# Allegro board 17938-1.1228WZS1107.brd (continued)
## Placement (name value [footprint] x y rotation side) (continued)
C6318  SC10U6D3V3MX-DL-GP  [C603H36]  39.02 28.49 180 bottom
C6319  SC2D2U10V3KX-L-GP  [C603H36]  159.4 115.4 0 bottom
C6320  SCD1U16V2KX-L-GP  [C402H22]  151.05 111.74 180 bottom
C6321  SC2D2U10V3KX-L-GP  [C603H36]  160.62 115.4 0 bottom
C6322  SC4D7U6D3V3KX-L-GP  [C603H36]  156.92 119.58 90 bottom
C6323  SCD1U16V2KX-L-GP  [C402H22]  151.81 111.74 180 bottom
C6324  SC4D7U6D3V3KX-L-GP  [C603H36]  156.92 118.37 90 bottom
C6401  SCD1U16V2KX-3GP  [C402H22]  210.37 56.47 90 bottom
C6405  SC1U6D3V1MX-GP  [C0201H14]  23.73 60.12 90 bottom
C6501  SCD1U16V2KX-3GP  [C402H22]  85.39 37.69 90 top
C6503  SCD1U16V2KX-3DLGP  [C402H22]  96.45 31.4 90 top
C6505  SCD1U16V2KX-3GP  [C402H22]  105.86 29.17 180 top
C6506  SC10P50V2JN-4DLGP  [C402H22]  101.27 36.5 180 bottom
C6507  SC10P50V2JN-4DLGP  [C402H22]  71.28 37.67 0 bottom
C6508  SC10P50V2JN-4DLGP  [C402H22]  88.09 37.29 0 top
C7003  SCD1U16V2KX-3DLGP  [C402H22]  144.33 78.44 0 top
C7004  SC10U6D3V3MX-GP  [C603H38]  145.32 78.54 0 top
C7103  SCD1U16V2KX-3DLGP  [C402H22]  28.04 101.35 270 top
C7104  SCD1U16V2KX-3DLGP  [C402H22]  28.04 100.56 270 top
C7105  SCD1U16V2KX-3DLGP  [C402H22]  28.04 99.77 270 top
C7106  SCD1U16V2KX-3DLGP  [C402H22]  28.04 98.99 270 top
C7107  SCD1U16V2KX-3DLGP  [C402H22]  27.38 105.31 270 top
C7108  SCD1U16V2KX-3DLGP  [C402H22]  27.36 106.91 270 top
C7109  SCD1U16V2KX-3DLGP  [C402H22]  27.36 106.15 270 top
C7110  SCD1U16V2KX-3DLGP  [C402H22]  27.05 108.46 270 top
C7111  SCD1U16V2KX-3DLGP  [C402H22]  27.05 107.67 270 top
C7112  SCD1U16V2KX-3DLGP  [C402H22]  27.38 103 270 top
C7113  SCD1U16V2KX-3DLGP  [C402H22]  27.38 103.76 270 top
C7114  SCD1U16V2KX-3DLGP  [C402H22]  27.38 104.55 270 top
C7115  SCD1U16V2KX-3DLGP  [C402H22]  20.45 103.23 180 bottom
C7116  SCD1U16V2KX-3DLGP  [C402H22]  20.1 107.63 0 bottom
C7117  SCD1U16V2KX-3DLGP  [C402H22]  22.81 103.35 180 bottom
C7118  SCD1U16V2KX-3DLGP  [C402H22]  22.07 108.27 0 bottom
C7119  SC10U6D3V3MX-DL-GP  [C603H36]  21.09 108.06 180 bottom
C7120  SCD1U16V2KX-3DLGP  [C402H22]  33.75 121.57 180 top
C7161  SCD1U25V2KX-1-DL-GP  [C402H22]  17.68 104.7 90 top
C7162  SCD1U25V2KX-1-DL-GP  [C402H22]  17.68 105.49 90 top
C7163  SCD1U25V2KX-1-DL-GP  [C402H22]  17.68 106.27 90 top
C7164  SCD1U25V2KX-1-DL-GP  [C402H22]  17.68 107.06 90 top
C7165  SC2D2U6D3V2MX-DL-GP  [C402H22]  18.8 101.63 180 top
C7166  SCD1U25V2KX-1-DL-GP  [C402H22]  23.42 107.33 270 bottom
C7167  SCD33U25V1KX-1-GP-U  [C0201-TO0D1H16]  17.48 103.66 270 top
C7168  SCD33U25V1KX-1-GP-U  [C0201-TO0D1H16]  18.09 108.33 270 top
C7169  SCD33U25V1KX-1-GP-U  [C0201-TO0D1H16]  18.09 107.77 270 top
C7170  SCD33U25V1KX-1-GP-U  [C0201-TO0D1H16]  17.45 102.92 270 top
C7201  SCD1U25V2KX-1-DL-GP  [C402H22]  44.53 107.18 270 top
C7202  SC1U6D3V1MX-GP  [C0201H14]  42.19 107.25 0 top
C7203  SCD1U16V2KX-3DLGP  [C402H22]  38.49 106.03 270 top
C7204  SCD1U16V2KX-3DLGP  [C402H22]  38.49 107.63 270 top
C7205  SCD1U16V2KX-3DLGP  [C402H22]  43.86 125.51 180 top
C7206  SC10U6D3V2MX-2-GP  [C402-TO0D2H28]  44.84 125.92 180 top
C7207  SC1U10V2KX-1GP  [C402H22]  38.49 106.82 270 top
C7208  SC390P50V2KX-GP-U  [C402H24]  43.44 112.55 180 top
C7209  SC390P50V2KX-GP-U  [C402H24]  44.96 110.29 90 top
C7210  SCD1U16V2KX-3DLGP  [C402H22]  41.51 105.92 90 top
C7211  SCD1U16V2KX-3DLGP  [C402H22]  41.51 105.13 90 top
C7212  SC1U10V2KX-1GP  [C402H22]  40.38 105.13 0 top
C7213  SCD1U16V2KX-3DLGP  [C402H22]  42.91 114.28 180 top
C7214  SC1U50V3KX-GP  [C603H32]  49.8 127.04 90 top
C7215  SCD22U10V2KX-1GP  [C402H22]  46.36 133.4 0 top
C7216  SCD1U16V2KX-3DLGP  [C402H22]  52.69 127.81 0 top
C7217  SC2D2U6D3V2MX-DL-GP  [C402H22]  53.47 127.8 0 top
C7302  SCD1U25V2KX-1-DL-GP  [C402H22]  11.66 125.05 0 bottom
C7303  SCD1U25V2KX-1-DL-GP  [C402H22]  10.57 118.02 270 top
C7304  SCD1U25V2KX-1-DL-GP  [C402H22]  12.45 125.05 0 bottom
C7305  SC10U25V5KX-DL-GP  [C805H58]  12.56 113.51 270 bottom
C7306  SC1U50V3KX-1-GP  [C603H36]  10.56 113.46 180 bottom
C7307  SCD1U25V2KX-1-DL-GP  [C402H22]  10.57 117.24 270 top
C7401  SC1500P50V2KX-2-DL-GP  [C402H22]  33.54 124.3 0 top
C7403  SC22U6D3V3MX-1-DL-GP  [C603H40]  44.94 122.04 90 top
C7404  SC22U6D3V3MX-1-DL-GP  [C603H40]  45.19 123.82 0 top
C7405  SC1KP50V2KX-1GP  [C402H22]  39.09 120.27 0 top
C9104  SCD1U16V2KX-3DLGP  [C402H22]  153.67 145.44 0 bottom
C9106  SC10U6D3V3MX-DL-GP  [C603H36]  147.09 145.04 0 bottom
C9108  SC33P50V2JN-3DLGP  [C402H22]  148.09 145.72 0 bottom
C9109  SC4D7U6D3V3KX-DLGP  [C603H36]  152.28 142.67 270 top
C9112  SCD1U16V2KX-3DLGP  [C402H22]  151.9 143.69 270 top
C9113  SCD1U16V2KX-3DLGP  [C402H22]  149.15 137.52 90 bottom
C9201  SC1U6D3V1MX-GP  [C0201H14]  213.8 63.68 180 top
C9202  SC1U6D3V1MX-GP  [C0201H14]  214.34 63.69 180 top
C9203  SCD1U16V2KX-3DLGP  [C402H22]  221.53 67.27 0 top
CPU1  WHISKEY-LAKE-GP  [BGA1528M2446-1H52]  100.25 95.3 270 bottom
D1701  RB520S30-GP  [SOD523AKH26]  143.87 83.24 180 bottom
D1702  BAW56-9-GP-U  [SOT23-2D4-312H44]  54.17 83.77 90 bottom
D2401  BAT54C-12-GP  [SOT-23-9H44]  21.62 40.41 270 bottom
D2402  L1SS355T1G-GP  [SOD323AKH44]  131.9 39.29 270 bottom
D2403  RB551V30-GP  [SOD323AKH38]  25.53 55.14 315 top
D2404  BAW56-9-GP-U  [SOT23-2D4-312H44]  52.47 80.25 270 bottom
D2501  BAT54C-12-GP  [SOT-23-9H44]  158.13 79.56 180 bottom
D2502  RB751VM-40TE-17-GP  [SOD323-2513AKH36]  161.71 82.77 90 bottom
D2503  BAT54A-11-GP  [SOT-23-9H44]  158.78 92.55 90 bottom
D2601  RB551V30-GP  [SOD323AKH38]  161.22 92.3 180 bottom
D2703  BAT54C-12-GP  [SOT-23-9H44]  22.86 22.18 180 top
D2901  BAT54A-11-GP  [SOT-23-9H44]  25.1 6.71 0 top
D4001  L1SS355T1G-GP  [SOD323AKH44]  142.55 117.36 180 bottom
D4002  RB520S30-GP  [SOD523AKH26]  83.77 40.26 90 bottom
D4003  RB520S30-GP  [SOD523AKH26]  87.07 40.23 270 bottom
D4301  P6AF24A-R1-00001-GP  [D4724AKH44]  22.03 121.72 90 top
D4302  LBAV99LT1G-1-GP  [SOT23-2D4-312H44]  25.25 92.41 90 top
D4304  SMF18A-GP  [SOD123AK-2H43]  150.23 38.98 180 bottom
D4305  RB751V-40H-GP  [SOD323AKH38]  35.57 133.41 90 top
D4309  RB751V-40H-GP  [SOD323AKH38]  34.98 131.65 90 top
D5502  BAT54C-12-GP  [SOT-23-9H44]  144.86 89.69 270 top
D5503  BAT54C-12-GP  [SOT-23-9H44]  180.83 69.62 90 bottom
D5504  RB751S40T1G-GP  [D1608AK-UH28]  145.32 131.57 180 top
D5505  RB751S40T1G-GP  [D1608AK-UH28]  150.99 134.06 0 top
D5701  BAW56-9-GP-U  [SOT23-2D4-312H44]  18.16 91.11 0 top
D6401  BAT54A-11-GP  [SOT-23-9H44]  27.21 24.44 180 top
D6403  RB751VM-40TE-17-GP  [SOD323-2513AKH36]  17.05 50.41 0 bottom
D7201  SBA0520Q-R1-00001-GP-U  [D1006-0305AK-UH22]  54.45 127.88 0 top
D7202  SBA0520Q-R1-00001-GP-U  [D1006-0305AK-UH22]  55.27 126.09 270 top
D7401  SBA330AH-R1-00001-GP  [SOD123AK-3718-1H40]  41.1 125.96 270 top
DBEC1  ACES-CON6-58-GP  [50696-00601-001]  46.54 74.76 90 top
DBG1  DM-ACES-CON14-5-GP-02  [DM-87212-1400N-02]  63.63 67.97 0 bottom
DCIN1  ACES-CON8-13-GP-U2  [50224-0080N-W02-U]  20.7 128.8 0 bottom
DM1  DDR4-260P-78-GP-U  [ADDR0206-P013A-1-U]  63.7 47 0 bottom
DM2  DDR4-260P-78-GP-U  [ADDR0206-P013A-1-U]  139.9 47 0 bottom
EC1202  SC2D2U6D3V2MX-DL-GP  [C402H22]  138.92 43.23 0 top
EC1203  SCD1U25V2KX-GP  [C402H22]  139.94 43.23 0 top
EC1303  SC2D2U6D3V2MX-DL-GP  [C402H22]  86.41 44.3 0 top
EC1707  SCD1U16V2KX-3DLGP  [C402H22]  138.31 83.64 90 bottom
EC1712  SCD1U16V2KX-3DLGP  [C402H22]  19.45 65.29 225 top
EC1801  SC10P50V2JN-4DLGP  [C402H22]  116.74 78.41 270 bottom
EC1803  SC4D7P50V2BN-2-GP  [C402H22]  25.17 79.88 270 top
EC1901  SC10P50V2JN-4DLGP  [C402H22]  26.92 18.37 270 top
EC1903  SC33P50V2JN-3DLGP  [C402H22]  27.48 19.15 270 top
EC2201  SCD1U16V2KX-3GP  [C402H22]  126.14 117.98 270 bottom
EC2501  SC4D7P50V2BN-2-GP  [C402H22]  152.75 95.29 0 bottom
EC2502  SC4D7P50V2BN-2-GP  [C402H22]  152.02 84.02 270 bottom
EC2503  SC10P50V2JN-4DLGP  [C402H22]  153.9 96.13 90 bottom
EC2504  SC10P50V2JN-4DLGP  [C402H22]  160.2 110.21 45 bottom
EC2505  SC4D7P50V2BN-2-GP  [C402H22]  156.31 111.18 90 bottom
EC2506  SC4D7P50V2BN-2-GP  [C402H22]  153.52 101.45 135 bottom
EC2601  SC10P50V2JN-4DLGP  [C402H22]  30.78 55.3 90 top
EC2602  SC10P50V2JN-4DLGP  [C402H22]  32.28 55.32 270 top
EC2701  SC1KP16V2KX-DL-GP  [C402H22]  20.02 20.37 180 top
EC2702  SC1KP16V2KX-DL-GP  [C402H22]  20.78 20.37 180 top
EC2703  SC1KP16V2KX-DL-GP  [C402H22]  34.56 5.33 45 top
EC2704  SC1KP16V2KX-DL-GP  [C402H22]  30.51 4.67 0 top
EC2705  SC1KP16V2KX-DL-GP  [C402H22]  22.92 4.62 0 top
EC2901  SC1KP50V2KX-1DLGP  [C402H22]  18.64 4.31 180 top
EC2902  SC1KP50V2KX-1DLGP  [C402H22]  19.48 5.01 0 top
EC2903  SC1KP50V2KX-1DLGP  [C402H22]  19.51 2.82 0 top
EC2904  SC1KP50V2KX-1DLGP  [C402H22]  18.7 1.89 180 top
EC2905  SC1KP16V2KX-DL-GP  [C402H22]  16.89 12.85 90 top
EC2906  SC1KP16V2KX-DL-GP  [C402H22]  18.29 18.34 90 top
EC2907  SC680P50V2KX-2DLGP  [C402H22]  20.4 10.44 90 top
EC2908  SC680P50V2KX-2DLGP  [C402H22]  18.29 11.13 270 top
EC3513  SC1KP16V2KX-DL-GP  [C402H22]  17.35 56.99 0 top
EC4301  SC10U25V5KX-DL-GP  [C805H58]  17.06 126.64 270 top
EC4302  SC1KP50V2KX-1GP  [C402H22]  20 127.69 270 top
EC4306  SC10P50V2JN-4GP  [C402H22]  134.85 35.61 90 top
EC4307  SC1KP50V2KX-1DLGP  [C402H22]  154.05 33.38 90 top
EC4308  SC1KP50V2KX-1GP  [C402H22]  142.14 40.59 90 bottom
EC4309  SC10P50V2JN-4GP  [C402H22]  134.85 37.16 270 top
EC4310  SC10P50V2JN-4GP  [C402H22]  134.85 36.37 270 top
EC4311  SCD1U25V2KX-GP  [C402H22]  19.76 124.01 90 top
EC4312  SC1KP50V2KX-1DLGP  [C402H22]  20 129.24 270 top
EC4313  SC1KP50V2KX-1GP  [C402H22]  20 128.48 270 top
EC4701  SC1KP16V2KX-DL-GP  [C402H22]  81.97 131.7 90 top
EC5001  SC1KP16V2KX-DL-GP  [C402H22]  109.32 119.94 90 top
EC5503  SC33P50V2JN-3DLGP  [C402H22]  216.21 45.26 270 top
EC5504  SC33P50V2JN-3DLGP  [C402H22]  215.6 43.21 90 top
EC6401  SCD1U16V2KX-3GP  [C402H22]  209.92 57.94 90 top
EC6402  SCD1U25V2KX-1-DL-GP  [C402H22]  10.44 129.57 0 bottom
EC6403  SC1KP50V2KX-1DLGP  [C402H22]  208.42 57.95 270 top
EC6404  SCD1U25V2KX-1-DL-GP  [C402H22]  13.95 129.62 270 bottom
EC6405  SCD1U25V2KX-1-DL-GP  [C402H22]  201.64 56.44 180 bottom
EC6501  SC33P50V2JN-3GP  [C402H22]  104.27 30.91 90 top
EC6502  SC33P50V2JN-3GP  [C402H22]  108.97 31.29 0 top
EC6503  SC33P50V2JN-3GP  [C402H22]  102.75 30.91 270 top
EC6504  SC33P50V2JN-3GP  [C402H22]  106.56 31.29 0 top
EC6601  SCD1U16V2KX-3DLGP  [C402H22]  200.66 38.83 270 top
EC8902  SC1KP16V2KX-DL-GP  [C402H22]  92.36 59.13 315 top
EC8904  SC1KP16V2KX-DL-GP  [C402H22]  106.81 64.41 135 top
EC8906  SC1KP16V2KX-DL-GP  [C402H22]  122.52 63.03 180 top
EC8909  SC1KP16V2KX-DL-GP  [C402H22]  141.02 62.51 135 top
EC8910  SC1KP16V2KX-DL-GP  [C402H22]  55.37 46.98 225 top
EC8911  SCD1U25V2KX-GP  [C402H22]  54.07 45.75 225 top
EC8912  SCD1U25V2KX-GP  [C402H22]  66.13 50.33 180 top
EC8913  SC1KP16V2KX-DL-GP  [C402H22]  111.39 46.34 180 top
EC8914  SCD1U25V2KX-GP  [C402H22]  115.58 46.39 180 top
EC8915  SCD1U25V2KX-GP  [C402H22]  162.43 45.45 270 top
EC8923  SC1KP50V2KX-1GP  [C402H22]  130.16 33.5 315 top
EC8924  SC1KP50V2KX-1GP  [C402H22]  130.72 32.94 315 top
EC8932  SCD1U25V2KX-GP  [C402H22]  163.35 128.35 90 bottom
EC8933  SC1U10V2KX-1DLGP  [C402H22]  204.75 31.98 90 top
EC8934  SC1U10V2KX-1DLGP  [C402H22]  168.23 34.9 315 top
EC8935  SC1U10V2KX-1DLGP  [C402H22]  168.13 36.12 270 top
EC8936  SC1U10V2KX-1DLGP  [C402H22]  174.63 31.55 270 top
EC8937  SC1U10V2KX-1DLGP  [C402H22]  191.37 31.75 90 top
EC8938  SC1U10V2KX-1DLGP  [C402H22]  73.1 35.66 45 top
EC8939  SC1U10V2KX-1DLGP  [C402H22]  98.1 40.18 270 top
EC8947  SC1U10V2KX-1DLGP  [C402H22]  61.98 126.67 270 bottom
EC8948  SC1U10V2KX-1DLGP  [C402H22]  52.5 42.29 90 top
EC8950  SC1U6D3V1MX-GP  [C0201H14]  58.14 130.1 270 bottom
EC8951  SC1U6D3V1MX-GP  [C0201H14]  180.01 71.76 270 bottom
EC8952  SC1U6D3V1MX-GP  [C0201H14]  36.55 34.24 180 top
EC8953  SC1U6D3V1MX-GP  [C0201H14]  54.89 130.35 270 top
EC8955  SC1KP50V2KX-1GP  [C402H22]  70.26 141.03 180 bottom
EC8956  SCD1U25V2KX-GP  [C402H22]  148.09 147.25 0 bottom
EC8962  SCD1U25V2KX-GP  [C402H22]  70.95 148.25 225 bottom
EC8963  SC1KP50V2KX-1GP  [C402H22]  146.72 147.1 180 bottom
ED301  AZ5125-02S-R7G-GP  [SOT23-2D4-312H46]  106.78 118.67 90 bottom
ED1217  PESD5V0U2BT-215-GP  [SOT23-2D4-312H44]  57.35 39.66 270 bottom
ED1302  PESD5V0U2BT-215-GP  [SOT23-2D4-312H44]  128.53 39.79 180 bottom
ED1701  PESD5V0S1BB-GP-U  [SOD-523-2H26]  155.08 140.11 180 bottom
ED1702  PESD5V0S1BB-GP-U  [SOD-523-2H26]  23.24 61.19 270 bottom
ED1703  PESD5V0S1BB-GP-U  [SOD-523-2H26]  71.93 136.64 180 top
ED1705  PESD5V0S1BB-GP-U  [SOD-523-2H26]  143.46 80.57 0 bottom
ED1706  PESD5V0S1BB-GP-U  [SOD-523-2H26]  31.6 56.7 270 top
ED1707  PESD5V0S1BB-GP-U  [SOD-523-2H26]  104.55 117.32 180 bottom
ED1801  PESD5V0S1BB-GP-U  [SOD-523-2H26]  141.1 89.46 270 top
ED1802  PESD5V0S1BB-GP-U  [SOD-523-2H26]  141.1 90.81 270 top
ED2403  AZ5125-02S-R7G-GP  [SOT23-2D4-312H46]  140.21 145.24 180 top
ED2910  AZ5125-02S-R7G-GP  [SOT23-2D4-312H46]  21.31 7.44 180 top
ED2911  AZ5125-02S-R7G-GP  [SOT23-2D4-312H46]  17.88 7.47 180 top
ED2912  AZ5125-02S-R7G-GP  [SOT23-2D4-312H46]  17.91 21.39 0 top
ED3201  AZ1043-04F-R7G-GP  [DFN10G2510H22]  40.78 84.41 90 bottom
ED3202  AZ1043-04F-R7G-GP  [DFN10G2510H22]  40.65 84.42 90 top
ED3501  AZ1043-04F-R7G-GP  [DFN10G2510H22]  17.07 53.57 270 bottom
ED3502  AZC099-04S-2-GP  [SOT-6H58]  18.04 47.04 270 bottom
ED3503  AZ1043-04F-R7G-GP  [DFN10G2510H22]  17.85 43.82 270 bottom
ED4303  AZ5725-01FDR7G-GP  [SOD882-10D6-1H20]  18.49 123.63 0 top
ED4304  LBAV99LT1G-1-GP  [SOT23-2D4-312H44]  125.09 37.3 180 bottom
ED4305  LBAV99LT1G-1-GP  [SOT23-2D4-312H44]  128.63 36.5 90 bottom
ED4306  LBAV99LT1G-1-GP  [SOT23-2D4-312H44]  123.15 39.81 180 bottom
ED5502  AZC099-04S-2-GP  [SOT-6H58]  214.1 47.84 270 bottom
ED5701  AZ1043-04F-R7G-GP  [DFN10G2510H22]  16.79 95.66 270 bottom
ED5702  AZ1043-04F-R7G-GP  [DFN10G2510H22]  16.79 98.71 90 bottom
ED5703  AZ1043-04F-R7G-GP  [DFN10G2510H22]  17.68 95.1 0 top
ED6001  AZ1043-04F-R7G-GP  [DFN10G2510H22]  164.15 38.71 0 top
ED6401  AZ5125-02S-R7G-GP  [SOT23-2D4-312H46]  211.48 54.48 0 bottom
ED6601  AZC099-04S-2-GP  [SOT-6H58]  202.35 41 90 bottom
ED7301  L05ESDL5V0NA-4-GP  [SLP2510P8-1H22]  11.62 116.19 270 bottom
ED7302  L05ESDL5V0NA-4-GP  [SLP2510P8-1H22]  11.31 127.31 270 bottom
ED7307  AZ5125-02S-R7G-GP  [SOT23-2D4-312H46]  17.57 121.14 270 top
ED7311  TVUFB0201AC0-GP  [SOD882-10D6-UH22]  11.44 123.73 90 bottom
ED7312  TVUFB0201AC0-GP  [SOD882-10D6-UH22]  11.43 122.4 90 bottom
ED7313  TVUFB0201AC0-GP  [SOD882-10D6-UH22]  11.74 121.51 90 bottom
ED7314  TVUFB0201AC0-GP  [SOD882-10D6-UH22]  11.76 120.22 90 bottom
ED7315  AZ5125-02S-R7G-GP  [SOT23-2D4-312H46]  11.81 119.33 180 top
ED9202  AZC099-04S-2-GP  [SOT-6H58]  207.78 55.42 270 bottom
EL3501  COIL-90OHM-100MHZ-5-GP  [L125100-4P-4H24]  19.21 49.79 270 bottom
EL3502  FILTER-4P-98-GP  [L125100-4P-5H24]  19.15 54.38 90 bottom
EL3503  FILTER-4P-98-GP  [L125100-4P-5H24]  19.18 52.83 90 bottom
EL3504  FILTER-4P-98-GP  [L125100-4P-5H24]  19.99 44.53 90 bottom
EL3505  FILTER-4P-98-GP  [L125100-4P-5H24]  21.85 42.92 90 bottom
EL3506  COIL-90OHM-100MHZ-5-GP  [L125100-4P-4H24]  21.88 46.09 180 bottom
EL4301  0R0805-PAD-1-GP-U  [0R0805-PAD-U]  24.14 127.44 90 top
EL4302  0R0805-PAD-1-GP-U  [0R0805-PAD-U]  21.78 128.69 180 top
EL4303  0R0805-PAD-1-GP-U  [0R0805-PAD-U]  16.53 128.96 180 top
EL4304  0R0805-PAD-1-GP-U  [0R0805-PAD-U]  18.34 128.96 180 top
EL5501  COIL-90OHM-100MHZ-5-GP  [L125100-4P-4H24]  211.18 48.54 0 bottom
EL5701  FILTER-4P-170-GP  [L125100-4P-3H24]  19.59 94.67 270 bottom
EL5702  FILTER-4P-170-GP  [L125100-4P-3H24]  19.61 96.22 270 bottom
EL5703  FILTER-4P-170-GP  [L125100-4P-3H24]  19.61 97.77 270 bottom
EL5704  FILTER-4P-170-GP  [L125100-4P-3H24]  19.61 99.34 270 bottom
EL6101  COIL-90OHM-100MHZ-5-GP  [L125100-4P-4H24]  31.78 97.64 0 top
EL6601  FILTER-4P-137-GP-U  [L125100-4P-4H28]  205.2 39.77 180 bottom
EL6602  FILTER-4P-137-GP-U  [L125100-4P-4H28]  205.2 41.34 180 bottom
EL7105  COIL-90OHM-100MHZ-5-GP  [L125100-4P-4H24]  28.91 117.93 180 top
EL7106  COIL-90OHM-100MHZ-5-GP  [L125100-4P-4H24]  36.22 116.56 270 top
ER5701  150R2F-1-GP  [R402H16]  15.05 94.72 0 bottom
ER5702  150R2F-1-GP  [R402H16]  15.05 96.42 0 bottom
ER5703  150R2F-1-GP  [R402H16]  15.05 98.12 0 bottom
ER5704  150R2F-1-GP  [R402H16]  15.05 99.82 0 bottom
F5503  POLYSW-1D1A24V-GP-U  [POLYSW-4633-UH43]  211.98 40.72 90 bottom
F5504  POLYSW-1D1A6V-9-GP-U  [POLYSW-2114H30]  213.21 46 180 top
F5505  POLYSW-1D1A6V-9-GP-U  [POLYSW-2114H30]  219.79 42.37 90 top
F5506  POLYSW-1D1A6V-9-GP-U  [POLYSW-2114H30]  224.42 40.78 270 top
F5701  POLYSW-1D1A6V-9-GP-U  [POLYSW-2114H30]  17.1 99.47 180 top
F6501  POLYSW-1D1A6V-9-GP-U  [POLYSW-2114H30]  80.88 36.34 180 bottom
FAN1  ACES-CON4-29-GP  [50224-0040N-001]  162.7 87.2 270 bottom
FC1102  SC2D2U6D3V2MX-DL-GP  [C402H22]  109.52 49.51 270 top
FC1103  SC2D2U6D3V2MX-DL-GP  [C402H22]  151.84 50.75 135 top
FC4534  SCD1U25V2KX-1-DL-GP  [C402H22]  155.1 147.12 180 bottom
FC5501  SC3D3P50V2CN-DL-GP  [C402H22]  215.19 55.02 90 top
FC5502  SC3D3P50V2CN-DL-GP  [C402H22]  215.19 55.78 90 top
FC5503  SC3D3P50V2CN-DL-GP  [C402H22]  215.19 53.49 90 top
FC5504  SC3D3P50V2CN-DL-GP  [C402H22]  215.19 54.26 90 top
FC5505  SC3D3P50V2CN-DL-GP  [C402H22]  215.19 51.97 90 top
FC5506  SC3D3P50V2CN-DL-GP  [C402H22]  215.19 52.73 90 top
FC8901  SCD1U16V2KX-3GP  [C402H22]  59.36 131.45 180 top
FC8902  SCD1U16V2KX-3GP  [C402H22]  44.15 27.99 270 bottom
FC8903  SC1U10V2KX-1GP  [C402H22]  64.14 39.14 180 top
FC8904  SC1U6D3V1MX-GP  [C0201H14]  137.11 107.04 0 bottom
FC8905  SC1U6D3V1MX-GP  [C0201H14]  71.96 131.19 270 top
FC8906  SC1U6D3V1MX-GP  [C0201H14]  79.37 103.01 180 top
FC8907  SCD1U16V2KX-3GP  [C402H22]  84.94 120.22 90 bottom
FC8908  SCD1U16V2KX-3GP  [C402H22]  103.28 115.55 90 top
FC8909  SC68P50V2JN-1DLGP  [C402H22]  84.56 126.54 270 top
FC8910  SCD1U16V2KX-3GP  [C402H22]  100.66 128.65 270 bottom
FC8911  SC68P50V2JN-1DLGP  [C402H22]  20.4 22.96 90 top
FC8912  SC68P50V2JN-1DLGP  [C402H22]  63.33 39.15 180 top
FC8913  SC68P50V2JN-1DLGP  [C402H22]  21.12 92.27 90 top
FC8914  SC68P50V2JN-1DLGP  [C402H22]  97.72 73.69 135 top
FC8915  SC68P50V2JN-1DLGP  [C402H22]  62.56 50.37 180 top
FC8916  SC68P50V2JN-1DLGP  [C402H22]  161.33 39.62 90 top
FC8917  SC68P50V2JN-1DLGP  [C402H22]  57.53 112.71 225 top
FC8918  SC68P50V2JN-1DLGP  [C402H22]  150.12 144.07 0 top
FC8919  SCD1U16V2KX-3GP  [C402H22]  59.89 121.96 270 top
FC8920  SCD1U16V2KX-3DLGP  [C402H22]  214.56 45.72 0 top
FC8921  SC68P50V2JN-1DLGP  [C402H22]  137.06 125.72 270 top
FC8922  SC68P50V2JN-1DLGP  [C402H22]  94.54 31.27 0 bottom
FC8923  SC68P50V2JN-1DLGP  [C402H22]  93.76 31.26 0 bottom
FC8924  SCD1U25V2KX-1-DL-GP  [C402H22]  92.99 31.27 0 bottom
FC8925  SCD1U25V2KX-1-DL-GP  [C402H22]  51.27 33.57 270 bottom
FC8926  SCD1U25V2KX-1-DL-GP  [C402H22]  51.26 32.79 270 bottom
FC8927  SC33P50V2JN-3DLGP  [C402H22]  71.53 148.85 45 bottom
FC8928  SC33P50V2JN-3DLGP  [C402H22]  72.09 149.4 45 bottom
FC8929  SC33P50V2JN-3DLGP  [C402H22]  72.65 149.96 45 bottom
FC8930  SCD1U25V2KX-1-DL-GP  [C402H22]  69.83 147.12 45 bottom
FC8931  SCD1U25V2KX-1-DL-GP  [C402H22]  79.59 145.5 180 bottom
FC8932  SCD1U25V2KX-GP  [C402H22]  96.39 144.87 180 bottom
FC8933  SCD1U25V2KX-GP  [C402H22]  181.29 47.68 0 top
FC8934  SCD1U25V2KX-GP  [C402H22]  180.46 47.67 0 top
FC8935  SCD1U25V2KX-GP  [C402H22]  89.16 28.37 0 top
FC8936  SCD1U25V2KX-GP  [C402H22]  88.27 28.37 0 top
FC8937  SCD1U25V2KX-GP  [C402H22]  137.85 130.28 135 top
FC8938  SCD1U25V2KX-GP  [C402H22]  137.28 130.84 135 top
FC8939  SCD1U25V2KX-1-DL-GP  [C402H22]  172.24 60.28 315 top
FC8940  SCD1U25V2KX-GP  [C402H22]  160.6 81.89 90 top
FC8941  SCD1U25V2KX-1-DL-GP  [C402H22]  160.6 82.67 90 top
FC8942  SCD1U25V2KX-1-DL-GP  [C402H22]  160.61 83.47 90 top
FC8943  SCD1U25V2KX-1-DL-GP  [C402H22]  156.31 81.13 180 top
FC8944  SCD1U25V2KX-GP  [C402H22]  77.24 145.49 180 bottom
FC8945  SCD1U25V2KX-1-DL-GP  [C402H22]  78.04 145.5 180 bottom
FC8946  SCD1U25V2KX-GP  [C402H22]  78.82 145.5 180 bottom
FC8947  SCD1U25V2KX-1-DL-GP  [C402H22]  97.17 144.87 180 bottom
FC8948  SCD1U25V2KX-GP  [C402H22]  80.39 145.49 180 bottom
FC8949  SCD1U25V2KX-GP  [C402H22]  85.6 28.37 0 top
FC8950  SCD1U25V2KX-GP  [C402H22]  80.65 28.25 0 top
FC8951  SCD1U25V2KX-GP  [C402H22]  97.94 144.87 180 bottom
FC8952  SCD1U25V2KX-GP  [C402H22]  126.16 144.25 180 bottom
FC8953  SCD1U25V2KX-GP  [C402H22]  110.19 145.38 180 bottom
FC8954  SCD1U25V2KX-GP  [C402H22]  111.35 145.38 180 bottom
FC8955  SCD1U25V2KX-GP  [C402H22]  112.16 145.38 180 bottom
FC8956  SC33P50V2JN-3DLGP  [C402H22]  112.92 145.38 180 bottom
FC8957  SCD1U25V2KX-GP  [C402H22]  144.28 147.25 180 bottom
FC8958  SC33P50V2JN-3DLGP  [C402H22]  145.04 147.25 180 bottom
FC8959  SC33P50V2JN-3DLGP  [C402H22]  143.51 147.25 180 bottom
FC8960  SCD1U25V2KX-GP  [C402H22]  163.56 141.22 90 bottom
FC8961  SCD1U25V2KX-GP  [C402H22]  163.56 141.98 90 bottom
FC8962  SCD1U25V2KX-GP  [C402H22]  163.56 142.74 90 bottom
FC8963  SCD1U25V2KX-GP  [C402H22]  76.16 144.88 225 bottom
FC8964  SCD1U25V2KX-GP  [C402H22]  163.46 134.26 90 bottom
FC8965  SCD1U25V2KX-GP  [C402H22]  163.45 137.97 90 bottom
FC8966  SCD1U25V2KX-GP  [C402H22]  163.46 138.76 90 bottom
FC8967  SCD1U25V2KX-GP  [C402H22]  163.56 143.5 90 bottom
FC8968  SCD1U25V2KX-GP  [C402H22]  137.49 38 0 top
FC8969  SCD1U25V2KX-GP  [C402H22]  136.73 38 0 top
FC8970  SCD1U25V2KX-GP  [C402H22]  135.97 38 0 top
FC8971  SC1500P50V2KX-2-DL-GP  [C402H22]  218.95 41.06 90 top
FC8972  SCD1U25V2KX-GP  [C402H22]  48.28 105.42 90 top
FC8973  SCD1U25V2KX-GP  [C402H22]  39.83 50.19 45 top
FC8974  SC1500P50V2KX-2-DL-GP  [C402H22]  214.38 43.36 0 bottom
FC8975  SCD1U16V2KX-3GP  [C402H22]  59.63 135.88 0 bottom
FC8976  SCD1U25V2KX-GP  [C402H22]  57.38 73.36 90 top
FC8977  SCD1U25V2KX-GP  [C402H22]  148.67 54.84 135 top
FC8978  SCD1U25V2KX-GP  [C402H22]  84.51 68.86 270 top
FC8979  SCD1U25V2KX-GP  [C402H22]  96.52 54.15 270 top
FC8980  SCD1U25V2KX-GP  [C402H22]  44.91 106.02 180 top
FC8981  SCD1U25V2KX-1-DL-GP  [C402H22]  163.35 129.21 90 bottom
FC8982  SCD1U25V2KX-GP  [C402H22]  63.76 140.29 90 bottom
FC8983  SCD1U25V2KX-GP  [C402H22]  163.33 130.05 90 bottom
FC8984  SCD1U25V2KX-GP  [C402H22]  163.46 133.39 90 bottom
FC8985  SCD1U25V2KX-GP  [C402H22]  155.91 147.11 180 bottom
FC8986  SCD1U25V2KX-GP  [C402H22]  150.45 147.25 180 bottom
FC8987  SCD1U25V2KX-GP  [C402H22]  149.66 147.25 180 bottom
FC8988  SCD1U25V2KX-GP  [C402H22]  148.87 147.25 180 bottom
FC8989  SCD1U25V2KX-GP  [C402H22]  125.38 144.25 0 bottom
FC8990  SCD1U16V2KX-3GP  [C402H22]  60.91 131.78 90 bottom
FP1  PTWO-CON8-11-GP  [FH52-8S-D5SH]  221.7 65.8 0 bottom
G1801  GAP-OPEN  [CON2O-U]  139.09 90.6 0 top
G6401  GAP-OPEN  [CON2O-U]  225.02 61.8 270 bottom
G6402  GAP-OPEN  [CON2O-U]  208.11 61.12 270 top
H9  HOLE335R178-GP  [HOLE335R178]  185.8 65.8 180 bottom
H10  HOLE335R178-GP  [HOLE335R178]  125.7 30.4 180 bottom
H11  HOLE256R115-GP  [HOLE256R115]  5.4 43.33 180 bottom
H12  HOLE335R229-GP  [HOLE335R229]  20.7 115.3 180 bottom
H13  HOLE256R115-GP  [HOLE256R115]  63.7 145.8 0 bottom
H14  HOLE256R115-GP  [HOLE256R115]  101.7 151.8 180 bottom
H16  HOLE335R178-GP  [HOLE335R178]  210.95 34.25 180 bottom
H17  HOLE256R115-GP  [HOLE256R115]  7.7 133.8 180 bottom
H18  HOLE256R115-GP  [HOLE256R115]  5.7 113.2 180 bottom
H19  HOLE233R142-GP-U1  [HOLE233R142]  68.01 108.27 180 bottom
H20  HOLE233R142-GP-U1  [HOLE233R142]  68.01 83.97 180 bottom
H21  HOLE233R142-GP-U1  [HOLE233R142]  129.01 83.97 180 bottom
H22  HOLE233R142-GP-U1  [HOLE233R142]  129.01 108.27 180 bottom
HDA27  ALC3204-CG-GP-U  [QFN40J5-G3D75H36]  26.93 13.77 0 top
HDD1  ACES-CON20-37-GP-U  [50406-02071-W01]  160.9 36.8 0 bottom
HDD2  STM-CON12-1-GP  [FFSKL05007N12C]  162.9 35.55 180 bottom
HDMI1  SKT-HDMI23-157-GP  [SKT-HDMI23-188139-2]  3.5 99.35 90 bottom
HPMIC1  AUDIO-JK677-GP  [14-00790-1A03-A]  3.41 15.2 90 bottom
HS3  STF237R113H86-GP  [STF237R113H86]  40.2 131.05 0 bottom
IOBD1  ACES-CON20-29-GP-U  [51530-02001-W01-U]  198.55 35.45 180 bottom
JUSB1  SKT-USB36-20-GP  [SKT-USB36-124102-1]  2.04 123.7 90 bottom
KB1  ACES-CON30-29-GP  [50699-03001-W01]  65.92 32.2 180 bottom
KBBL1  ACES-CON4-90-GP-U  [50698-00401-W01-U]  86.84 32.1 180 bottom
L7101  MCB1005H470FBP-GP  [L402H24]  17.28 109.37 270 bottom
LCD1  STAR-CON40-8-GP  [300E40-1010RA-G3]  221.7 47.3 270 bottom
LED1  LED-YW-5-GP  [LED3020-3P-19H44]  2.7 134.8 0 bottom
LED2  LED-Y-102-GP  [LED11516AKH28]  9.7 65.8 0 bottom
MESW1  SW-SLIDE3P-11-GP  [MSS3-Q-T-R]  13.15 43.33 270 bottom
NOREF  -  []  30.2 102.8 0 top
NOREF#2  -  []  11.9 82.9 90 top
NOREF#3  -  []  2.72 116.92 0 top
NOREF#4  -  []  60.73 72.56 0 top
NOREF#5  -  []  177.12 41.03 0 top
NOREF#6  -  []  17.83 107.77 0 top
NOREF#7  -  []  4.01 10.35 90 top
NOREF#8  -  []  152.9 27.48 90 top
NOREF#9  -  []  125.3 159.44 0 top
NOREF#10  -  []  -0.25 67.47 90 top
NOREF#11  -  []  151.34 38.65 0 top
NOREF#12  -  []  158.2 134.86 90 top
NOREF#13  -  []  153.75 37.13 0 top
NOREF#14  -  []  125.85 153.44 0 top
NOREF#15  -  []  12.24 24.6 90 top
NOREF#16  -  []  51.4 96.63 90 top
NOREF#17  -  []  3.41 15.2 0 top
NOREF#18  -  []  173.72 32.66 90 top
NOREF#19  -  []  11.92 116.84 90 top
NOREF#20  -  []  -11.3 15.8 0 top
NOREF#21  -  []  168.05 36.8 90 top
NOREF#22  -  []  152.9 27.48 90 top
NOREF#23  -  [unnamed#2]  3.7 7.3 0 top
NOREF#24  -  []  160.9 36.8 90 top
NOREF#25  -  []  -1.8 127.92 0 top
NOREF#26  *  [unnamed#2]  17.58 86.26 0 top
NOREF#27  -  []  177.4 58.08 90 top
NOREF#28  -  []  3.41 15.2 0 top
NOREF#29  -  []  194.95 58.85 90 top
NOREF#30  -  []  13.14 54.65 90 top
NOREF#31  -  []  2.72 116.92 0 top
NOREF#32  -  []  51.4 104.88 0 top
NOREF#33  -  []  19.08 29.66 90 top
NOREF#34  -  []  188 32.1 0 top
NOREF#35  -  []  5.44 23.15 90 top
NOREF#36  -  []  177.4 58.08 90 top
NOREF#37  -  []  2.75 85.05 90 top
NOREF#38  *  [unnamed#2]  42.95 4.9 0 top
NOREF#39  -  []  192.55 60.8 90 top
NOREF#40  -  []  -3.99 26.86 0 top
NOREF#41  -  []  131.3 158.89 0 top
NOREF#42  -  []  184.83 57.48 0 top
NOREF#43  -  []  -7.69 18.9 0 top
NOREF#44  -  []  162.16 28.49 90 top
NOREF#45  -  []  51.4 96.63 90 top
NOREF#46  -  []  177.12 38.16 90 top
NOREF#47  *  [unnamed#2]  85.68 34.52 0 top
NOREF#48  -  []  11.64 27 90 top
NOREF#49  -  []  12.24 37.4 90 top
NOREF#50  -  []  230.99 133.09 270 top
NOREF#51  -  []  81.2 82.3 0 top
NOREF#52  -  []  11.64 59.65 90 top
NOREF#53  -  []  11.92 116.84 90 top
NOREF#54  -  []  125.3 109.35 90 top
NOREF#55  -  []  158.2 132.86 90 top
NOREF#56  -  []  -1.8 127.92 0 top
NOREF#57  -  []  192.55 60.8 0 top
NOREF#58  -  []  156.31 132.86 0 top
NOREF#59  -  []  17.2 102.92 0 top
NOREF#60  -  []  147.39 109.89 90 top
NOREF#61  -  []  155.87 132.31 0 top
NOREF#62  -  []  125.85 153.44 0 top
NOREF#63  -  []  5.44 47.8 90 top
NOREF#64  -  []  30.2 102.8 0 top
NOREF#65  *  [unnamed#2]  122.05 79.43 0 top
NOREF#66  -  []  164.8 34.85 90 top
NOREF#67  -  []  53.29 105.98 0 top
NOREF#68  -  []  4.01 10.35 0 top
NOREF#69  -  []  70.41 150.83 0 top
NOREF#70  -  []  -2.06 85.96 0 top
NOREF#71  -  []  185.61 56.26 0 top
NOREF#72  -  []  156.31 132.86 0 top
NOREF#73  -  []  5.44 23.15 90 top
NOREF#74  -  []  147.39 110.39 90 top
NOREF#75  -  []  188 32.1 90 top
NOREF#76  -  []  182.02 37.76 0 top
NOREF#77  -  []  174.05 93.24 180 top
NOREF#78  -  []  -6.35 82.92 0 top
NOREF#79  -  []  -0.81 48.84 0 top
NOREF#80  -  []  189.17 33.8 90 top
NOREF#81  -  []  5.44 47.8 90 top
NOREF#82  -  []  51.4 104.88 0 top
NOREF#83  -  [unnamed#2]  213.42 76.93 0 top
NOREF#84  -  []  6 85.85 0 top
NOREF#85  *  [unnamed#2]  219.73 149.97 0 top
NOREF#86  -  []  88.02 51.62 0 top
NOREF#87  -  []  194.95 58.85 0 top
NOREF#88  -  []  195.8 62.75 0 top
NOREF#89  -  []  -3.99 15.2 90 top
NOREF#90  -  []  -0.14 18.9 0 top
NOREF#91  -  []  186.83 40.3 90 top
NOREF#92  -  []  2.72 116.92 0 top
NOREF#93  -  []  156.15 38.75 0 top
NOREF#94  -  []  11.64 27 90 top
NOREF#95  -  []  -11.3 15.8 0 top
NOREF#96  -  []  5.57 11.29 90 top
NOREF#97  -  []  12.24 62.05 90 top
NOREF#98  -  []  77.94 84.44 0 top
NOREF#99  -  []  158.2 134.86 90 top
NOREF#100  -  []  11.92 116.84 90 top
NOREF#101  -  []  45.54 51.54 0 top
NOREF#102  -  []  -1.48 63.96 0 top
NOREF#103  -  []  -1.8 127.92 0 top
NOREF#104  -  []  -0.81 48.84 90 top
NOREF#105  -  []  199.7 60.8 90 top
NOREF#106  -  []  150.77 36.81 0 top
NOREF#107  *  [unnamed#2]  132.7 117.77 0 top
NOREF#108  -  []  12.85 80.22 90 top
NOREF#109  -  []  202.45 58.85 0 top
NOREF#110  -  []  19.08 54.31 90 top
NOREF#111  -  []  59.46 72.56 0 top
NOREF#112  -  []  173.72 35.53 0 top
NOREF#113  -  []  3.41 19.9 0 top
NOREF#114  -  []  11.92 116.84 90 top
NOREF#115  -  []  -2.1 11.29 0 top
NOREF#116  -  []  12.85 80.22 0 top
NOREF#117  -  []  186.83 41.3 0 top
NOREF#118  -  []  125.85 115.34 90 top
NOREF#119  -  []  64.54 72.56 0 top
NOREF#120  -  []  51.4 96.63 90 top
NOREF#121  -  []  77.25 83.3 0 top
NOREF#122  -  []  184.83 54.61 90 top
NOREF#123  -  []  -11.3 15.8 0 top
NOREF#124  -  []  12.85 80.22 0 top
NOREF#125  -  []  21.33 21.86 90 top
NOREF#126  -  []  56.95 72.58 0 top
NOREF#127  -  []  153.75 36.8 0 top
NOREF#128  -  []  4.01 10.35 90 top
NOREF#129  -  []  -1.48 39.31 0 top
NOREF#130  -  []  125.85 115.34 90 top
NOREF#131  -  []  3.41 15.2 0 top
NOREF#132  -  []  2.75 68.25 90 top
NOREF#133  -  []  5.28 47.01 0 top
NOREF#134  -  []  153.68 39.54 0 top
NOREF#135  -  []  -11.3 15.8 0 top
NOREF#136  -  []  51.4 96.63 90 top
NOREF#137  -  []  58.19 72.56 0 top
NOREF#138  -  []  21.33 46.51 90 top
NOREF#139  *  [unnamed#2]  227 31.45 0 top
NOREF#140  -  []  186.83 41.3 0 top
NOREF#141  -  []  147.39 110.39 90 top
NOREF#142  -  []  24.56 152.99 180 top
NOREF#143  -  []  190.07 44.05 90 top
NOREF#144  -  []  186.83 41.3 0 top
NOREF#145  -  []  63.27 72.56 0 top
NOREF#146  -  []  53.29 105.98 0 top
NOREF#147  -  []  151.34 28.49 90 top
NOREF#148  -  []  125.85 115.34 90 top
NOREF#149  -  []  12.24 49.25 90 top
NOREF#150  -  []  147.39 110.39 90 top
NOREF#151  -  []  30.2 102.8 0 top
NOREF#152  -  []  158.37 133.01 0 top
NOREF#153  -  []  75.85 150.8 0 top
NOREF#154  -  []  -0.81 24.19 0 top
NOREF#155  -  []  184.11 39.42 90 top
NOREF#156  -  []  125.3 109.35 90 top
NOREF#157  -  []  52.05 59.07 0 top
NOREF#158  -  []  11.64 51.65 90 top
NOREF#159  -  []  13.14 27.5 90 top
NOREF#160  -  []  51.4 96.63 90 top
NOREF#161  *  [unnamed#2]  5.06 148.02 0 top
NOREF#162  -  []  5.28 22.36 0 top
NOREF#163  -  []  30.2 102.8 0 top
NOREF#164  -  []  -0.25 67.47 90 top
NOREF#165  -  []  190.07 48.19 0 top
NOREF#166  -  []  131.3 158.89 0 top
NOREF#167  -  []  13.14 52.15 90 top
NOREF#168  -  []  1.44 82.45 0 top
NOREF#169  -  []  51.4 96.63 90 top
NOREF#170  -  [unnamed#2]  43 145.81 0 top
NOREF#171  -  [unnamed#2]  105.66 9.55 0 top
NOREF#172  -  []  11.64 35 90 top
NOREF#173  *  [unnamed#2]  176.94 146.43 0 top
NOREF#174  -  []  77.94 85.09 90 top
NOREF#175  -  []  13.14 34.5 90 top
NOREF#176  -  []  125.3 109.35 90 top
NOREF#177  -  []  -11.3 15.8 0 top
NOREF#178  -  []  -3.99 26.86 0 top
NOREF#179  -  []  13.95 73.08 90 top
NOREF#180  -  []  -11.3 15.8 0 top
NOREF#181  -  []  17.83 108.33 0 top
NOREF#182  -  []  157 34.85 0 top
NOREF#183  -  []  4.85 86.35 90 top
NOREF#184  -  []  217.74 130.29 180 top
NOREF#185  -  []  3.41 19.9 0 top
NOREF#186  -  []  155.87 132.31 0 top
NOREF#187  -  []  -0.25 79.55 0 top
NOREF#188  -  []  158.64 132.31 90 top
NOREF#189  -  [unnamed#2]  183.63 148.09 0 top
NOREF#190  *  [unnamed#2]  3.97 3.68 0 top
NOREF#191  -  []  3.41 19.9 90 top
NOREF#192  -  [unnamed#2]  -3.26 43.25 0 top
NOREF#193  -  []  11.92 116.84 90 top
NOREF#194  -  []  -0.25 67.47 90 top
NOREF#195  -  []  4.01 10.35 0 top
NOREF#196  -  []  13.14 59.15 90 top
NOREF#197  -  []  62 72.56 0 top
NOREF#198  -  []  -0.81 24.19 90 top
NOREF#199  -  []  -1.8 127.92 0 top
NOREF#200  -  []  184.11 42.29 0 top
NOREF#201  -  []  92.05 83.99 90 top
NOREF#202  -  []  2.75 85.05 0 top
NOREF#203  -  []  157.65 38.75 0 top
NOREF#204  -  []  125.85 153.44 0 top
NOREF#205  -  []  131.3 158.89 0 top
NOREF#206  -  []  158.2 132.86 90 top
NOREF#207  -  []  51.4 96.63 90 top
NOREF#208  -  []  178.25 67.73 0 top
NOREF#209  -  []  175.47 38.95 90 top
NOREF#210  *  [unnamed#2]  67.06 150.8 0 top
NOREF#211  -  []  125.3 159.44 0 top
NOREF#212  -  []  3.41 19.9 0 top
NOREF#213  -  []  151.34 28.49 90 top
NOREF#214  -  []  177.4 64.1 0 top
NOREF#215  -  []  11.64 51.65 90 top
NOREF#216  -  []  125.3 159.44 0 top
NOREF#217  -  []  152.9 33.5 90 top
NOREF#218  -  []  -1.8 127.92 0 top
NOREF#219  -  []  -0.25 67.47 90 top
NOREF#220  -  []  13.14 30 90 top
NOREF#221  *  [unnamed#2]  167.39 150.93 0 top
NOREF#222  -  []  158.64 132.31 90 top
NOREF#223  -  []  -2.69 56.78 0 top
NOREF#224  -  []  17.22 103.66 0 top
NOREF#225  -  []  3.41 19.9 90 top
NOREF#226  -  []  199.7 60.8 90 top
NOREF#227  -  []  -2.69 32.13 0 top
NOREF#228  -  [unnamed#2]  45.12 18.33 0 top
NOREF#229  *  [unnamed#2]  193.32 64.42 0 top
NOREF#230  -  []  51.4 96.63 90 top
NOREF#231  -  []  172.07 33.44 90 top
NOREF#232  -  []  -11.91 21.69 90 top
NOREF#233  -  []  3.41 15.2 90 top
NOREF#234  -  []  152.9 33.5 0 top
NOREF#235  -  [unnamed#2]  58.2 141.2 0 top
NOREF#236  -  []  51.4 96.63 90 top
NOREF#237  *  [unnamed#2]  5.06 148.02 180 bottom
NOREF#238  -  []  142.07 124.21 180 bottom
NOREF#239  -  []  19.55 10.89 180 bottom
NOREF#240  *  [unnamed#2]  219.73 149.97 180 bottom
NOREF#241  -  []  38.79 121.62 180 bottom
NOREF#242  -  []  582.8 15.57 180 bottom
NOREF#243  -  []  582.8 14.57 180 bottom
NOREF#244  *  [unnamed#2]  42.95 4.9 180 bottom
NOREF#245  *  [unnamed#2]  157.08 136.12 180 bottom
NOREF#246  *  [unnamed#2]  67.06 150.8 180 bottom
NOREF#247  *  [unnamed#2]  167.39 150.93 180 bottom
NOREF#248  -  []  585.07 15.8 180 bottom
NOREF#249  -  []  159.52 66.4 180 bottom
NOREF#250  -  []  75.85 150.8 180 bottom
NOREF#251  -  []  585.07 10.08 180 bottom
NOREF#252  *  [unnamed#2]  58.17 79.68 180 bottom
NOREF#253  *  [unnamed#2]  3.97 3.68 180 bottom
NOREF#254  *  [unnamed#2]  227 31.45 180 bottom
NOREF#255  -  []  230.99 116.31 90 bottom
NOREF#256  -  []  154.9 127.85 180 bottom
NOREF#257  -  []  18.6 138.99 180 bottom
NOREF#258  *  [unnamed#2]  176.94 146.43 180 bottom
ODD1  ACES-CONN16D-5-GP  [50552-01601-001]  188 37.55 270 bottom
PC1001  SC22U6D3V3MX-1-DL-GP  [C603H40]  82.48 130.71 90 top
PC1002  SC22U6D3V3MX-1-DL-GP  [C603H40]  103.23 117.7 90 top
PC1003  SC22U6D3V3MX-1-DL-GP  [C603H40]  103.23 118.97 90 top
PC1004  SC22U6D3V3MX-1-DL-GP  [C603H40]  103.23 120.24 90 top
PC1005  SC22U6D3V3MX-1-DL-GP  [C603H40]  103.28 125.15 90 top
PC1006  SC22U6D3V3MX-1-DL-GP  [C603H40]  102.77 98.15 90 top
PC1007  SC22U6D3V3MX-1-DL-GP  [C603H40]  84.53 119.66 270 top
PC1008  SC22U6D3V3MX-1-DL-GP  [C603H40]  103.25 122.63 90 top
PC1009  SC22U6D3V3MX-1-DL-GP  [C603H40]  84.55 122.03 270 top
PC1010  SC22U6D3V3MX-1-DL-GP  [C603H40]  102.77 94.57 90 top
PC1011  SC22U6D3V3MX-1-DL-GP  [C603H40]  102.78 95.77 90 top
PC1012  SC22U6D3V3MX-1-DL-GP  [C603H40]  84.53 118.48 270 top
PC1013  SC22U6D3V3MX-1-DL-GP  [C603H40]  103.26 123.94 90 top
PC1014  SC22U6D3V3MX-1-DL-GP  [C603H40]  102.77 99.34 90 top
PC1015  SC22U6D3V3MX-1-DL-GP  [C603H40]  97.06 90.7 270 top
PC1016  SC22U6D3V3MX-1-DL-GP  [C603H40]  84.55 124.39 270 top
PC1017  SC22U6D3V3MX-1-DL-GP  [C603H40]  102.77 96.95 90 top
PC1018  SC22U6D3V3MX-1-DL-GP  [C603H40]  84.53 120.83 270 top
PC1019  SC22U6D3V3MX-1-DL-GP  [C603H40]  103.23 116.54 90 top
PC1020  SC22U6D3V3MX-1-DL-GP  [C603H40]  96.6 99.2 90 top
PC1021  SC22U6D3V3MX-1-DL-GP  [C603H40]  96.6 96.84 90 top
PC1022  SC22U6D3V3MX-1-DL-GP  [C603H40]  99.66 94.51 270 top
PC1023  SC22U6D3V3MX-1-DL-GP  [C603H40]  99.66 95.68 270 top
PC1024  SC22U6D3V3MX-1-DL-GP  [C603H40]  99.66 96.85 270 top
PC1025  SC22U6D3V3MX-1-DL-GP  [C603H40]  99.66 98.02 270 top
PC1026  SC22U6D3V3MX-1-DL-GP  [C603H40]  99.66 99.19 270 top
PC1027  SC22U6D3V3MX-1-DL-GP  [C603H40]  96.6 93.31 90 top
PC1028  SC22U6D3V3MX-1-DL-GP  [C603H40]  84.53 125.58 270 top
PC1029  SC22U6D3V3MX-1-DL-GP  [C603H40]  84.55 123.2 270 top
PC1030  SC22U6D3V3MX-1-DL-GP  [C603H40]  103.25 121.41 90 top
PC1031  SC22U6D3V3MX-1-DL-GP  [C603H40]  96.6 98.01 90 top
PC1032  SC22U6D3V3MX-1-DL-GP  [C603H40]  93.38 96.04 270 top
PC1034  SC22U6D3V3MX-1-DL-GP  [C603H40]  93.39 94.84 270 top
PC1036  SC22U6D3V3MX-1-DL-GP  [C603H40]  84.54 117.3 270 top
PC1037  SC22U6D3V3MX-1-DL-GP  [C603H40]  73.03 100.61 270 top
PC1038  SC22U6D3V3MX-1-DL-GP  [C603H40]  87.25 99.24 0 top
PC1039  SC22U6D3V3MX-1-DL-GP  [C603H40]  83.7 92.89 0 top
PC1040  SC22U6D3V3MX-1-DL-GP  [C603H40]  79.51 93.42 270 top
PC1041  SC22U6D3V3MX-1-DL-GP  [C603H40]  88.09 96.14 180 top
PC1042  SC22U6D3V3MX-1-DL-GP  [C603H40]  82.15 118.7 90 top
PC1043  SC22U6D3V3MX-1-DL-GP  [C603H40]  72.09 115.72 270 top
PC1044  SC22U6D3V3MX-1-DL-GP  [C603H40]  85.7 96.14 180 top
PC1045  SC22U6D3V3MX-1-DL-GP  [C603H40]  84.51 96.14 180 top
PC1046  SC22U6D3V3MX-1-DL-GP  [C603H40]  86.06 99.24 0 top
PC1047  SC22U6D3V3MX-1-DL-GP  [C603H40]  79.51 94.59 270 top
PC1048  SC22U6D3V3MX-1-DL-GP  [C603H40]  73.03 102.95 270 top
PC1049  SC22U6D3V3MX-1-DL-GP  [C603H40]  82.47 129.52 90 top
PC1050  SC22U6D3V3MX-1-DL-GP  [C603H40]  82.15 127.15 90 top
PC1051  SC22U6D3V3MX-1-DL-GP  [C603H40]  82.15 125.93 90 top
PC1052  SC22U6D3V3MX-1-DL-GP  [C603H40]  82.17 128.35 90 top
PC1053  SC22U6D3V3MX-1-DL-GP  [C603H40]  73.08 97.03 270 top
PC1054  SC22U6D3V3MX-1-DL-GP  [C603H40]  83.67 99.24 0 top
PC1055  SC22U6D3V3MX-1-DL-GP  [C603H40]  73.03 101.78 270 top
PC1056  SC22U6D3V3MX-1-DL-GP  [C603H40]  73.1 98.22 270 top
PC1057  SC22U6D3V3MX-1-DL-GP  [C603H40]  72.09 116.99 270 top
PC1058  SC22U6D3V3MX-1-DL-GP  [C603H40]  84.86 99.24 0 top
PC1059  SC22U6D3V3MX-1-DL-GP  [C603H40]  82.15 119.91 90 top
PC1060  SC22U6D3V3MX-1-DL-GP  [C603H40]  86.9 96.14 180 top
PC1061  SC22U6D3V3MX-1-DL-GP  [C603H40]  90.86 93.04 0 top
PC1062  SC22U6D3V3MX-1-DL-GP  [C603H40]  73.1 99.42 270 top
PC1063  SC22U6D3V3MX-1-DL-GP  [C603H40]  82.15 122.35 90 top
PC1064  SC22U6D3V3MX-1-DL-GP  [C603H40]  82.15 123.55 90 top
PC1065  SC22U6D3V3MX-1-DL-GP  [C603H40]  82.15 121.13 90 top
PC1066  SC22U6D3V3MX-1-DL-GP  [C603H40]  82.73 96.37 90 top
PC1067  SC22U6D3V3MX-1-DL-GP  [C603H40]  82.15 124.74 90 top
PC1068  SC22U6D3V3MX-1-DL-GP  [C603H40]  89.28 96.14 180 top
PC1069  SC22U6D3V3MX-1-DL-GP  [C603H40]  90.48 96.14 180 top
PC1070  SC22U6D3V3MX-1-DL-GP  [C603H40]  82.15 117.53 90 top
PC1071  SC22U6D3V3MX-1-DL-GP  [C603H40]  105.18 99.34 270 top
PC1072  SC22U6D3V3MX-1-DL-GP  [C603H40]  105.9 93.37 270 top
PC1073  SC22U6D3V3MX-1-DL-GP  [C603H40]  105.9 98.12 270 top
PC1074  SC22U6D3V3MX-1-DL-GP  [C603H40]  109.31 120.95 90 top
PC1075  SC22U6D3V3MX-1-DL-GP  [C603H40]  109.31 122.22 90 top
PC1076  SC22U6D3V3MX-1-DL-GP  [C603H40]  105.9 94.57 270 top
PC1077  SC22U6D3V3MX-1-DL-GP  [C603H40]  105.9 95.78 270 top
PC1078  SC22U6D3V3MX-1-DL-GP  [C603H40]  105.9 96.95 270 top
PC1079  SC22U6D3V3MX-1-DL-GP  [C603H40]  102.64 90.96 90 top
PC1080  SC22U6D3V3MX-1-DL-GP  [C603H40]  96.6 95.67 90 top
PC1081  SC22U6D3V3MX-1-DL-GP  [C603H40]  96.6 94.49 90 top
PC1082  SC22U6D3V3MX-1-DL-GP  [C603H40]  93.39 93.66 270 top
PC1083  SC22U6D3V3MX-1-DL-GP  [C603H40]  99.67 93.33 270 top
PC1084  SC22U6D3V3MX-1-DL-GP  [C603H40]  102.77 93.38 90 top
PC4402  SC10U25V5KX-DL-GP  [C805H58]  196.94 52.37 180 bottom
PC4403  SC10U25V5KX-DL-GP  [C805H58]  193.79 56.33 270 bottom
PC4404  SC10U25V5KX-DL-GP  [C805H58]  189.33 60.02 0 bottom
PC4405  SC10U25V5KX-DL-GP  [C805H58]  189.31 56.01 180 bottom
PC4406  SCD1U25V2KX-1-DL-GP  [C402H22]  150.49 39.8 180 top
PC4407  SC10U25V5KX-DL-GP  [C805H58]  181 57.89 270 bottom
PC4408  SC10U25V3MX-3-GP  [C603H40]  184.05 31.64 270 bottom
PC4409  SC10U25V3MX-3-GP  [C603H40]  184.05 33.99 270 bottom
PC4410  SC10U25V3MX-3-GP  [C603H40]  184.05 32.82 270 bottom
PC4411  SC10U25V3MX-3-GP  [C603H40]  181.86 31.9 180 bottom
PC4412  SC10U25V5KX-DL-GP  [C805H58]  180.23 63.12 270 bottom
PC4413  SC10U25V3MX-3-GP  [C603H40]  180.65 31.9 180 bottom
PC4414  SC10U25V3MX-3-GP  [C603H40]  184.04 35.19 270 bottom
PC4415  SC4D7U25V3KX-GP  [C603H40]  203.86 53.75 270 bottom
PC4416  SC1U25V3KX-1-DLGP  [C603H36]  207.37 52.55 90 bottom
PC4417  SC1U25V3KX-1-DLGP  [C603H36]  201.83 54.51 180 bottom
PC4418  SC10U25V5KX-DL-GP  [C805H58]  180.04 59.62 270 bottom
PC4419  SC1U25V3KX-1-DLGP  [C603H36]  207.45 51.33 270 bottom
PC4420  SCD022U16V2KX-3DLGP  [C402H22]  203.92 51.16 180 top
PC4421  SC4D7U6D3V3KX-DLGP  [C603H36]  199 51.79 90 bottom
PC4422  SC4D7U6D3V3KX-DLGP  [C603H36]  207.5 50.15 270 bottom
PC4423  SCD22U25V3KX-DL-GP  [C603H36]  198 47.94 90 bottom
PC4424  SC1U25V3KX-1-DLGP  [C603H36]  196.22 46.41 180 bottom
PC4425  SC1U25V3KX-1-DLGP  [C603H36]  197.41 45 180 bottom
PC4426  SC1U25V3KX-1-DLGP  [C603H36]  196.22 44.04 0 bottom
PC4427  SC10U25V3MX-3-GP  [C603H40]  178.27 31.9 180 bottom
PC4429  SC4700P50V2KX-1DLGP  [C402H22]  176.53 34.67 225 top
PC4430  SC10P50V2JN-4DLGP  [C402H22]  205.26 47.24 270 top
PC4431  SCD01U25V2KX-3DLGP  [C402H22]  195.1 44.48 0 top
PC4432  SC1KP50V2KX-1DLGP  [C402H22]  202.92 43.51 270 bottom
PC4433  SC470P50V2KX-3DLGP  [C402H22]  196.24 44.1 270 top
PC4434  SC10U25V5KX-DL-GP  [C805H58]  180.17 66.5 0 bottom
PC4435  SC1KP50V2KX-1DLGP  [C402H22]  190.76 48.31 0 top
PC4436  SCD22U25V3KX-DL-GP  [C603H36]  199.42 55.66 0 bottom
PC4437  SC10U25V5KX-DL-GP  [C805H58]  180.04 61.38 270 bottom
PC4438  SCD1U16V2KX-3DLGP  [C402H22]  149.36 145.59 180 top
PC4439  SC1U25V3KX-1-DLGP  [C603H36]  198 46.77 270 bottom
PC4440  SC1U25V3KX-1-DLGP  [C603H36]  201.58 44.44 0 bottom
PC4441  SC2200P50V2KX-2DLGP  [C402H22]  204.11 47.24 180 top
PC4442  SC1KP50V2KX-1DLGP  [C402H22]  199.32 52.86 270 top
PC4443  SC2200P50V2KX-2GP  [C402H22]  178.06 36.35 270 top
PC4445  SC1KP50V2KX-1DLGP  [C402H22]  200.72 46.03 90 bottom
PC4446  SC10U25V5KX-DL-GP  [C805H58]  146.94 40.01 0 bottom
PC4447  SC10U25V3MX-3-GP  [C603H40]  148.44 40.06 0 bottom
PC4448  SC10U25V3MX-3-GP  [C603H40]  179.44 31.9 180 bottom
PC4449  SCD1U16V2KX-3DLGP  [C402H22]  11.07 123.01 90 top
PC4501  SCD1U25V2KX-GP  [C402H22]  69.07 140.97 180 bottom
PC4502  SC10U25V5KX-DL-GP  [C805H58]  67.29 139.52 270 bottom
PC4503  SC10U25V5KX-DL-GP  [C805H58]  63.66 138.81 90 bottom
PC4504  SC10U25V5KX-DL-GP  [C805H58]  63.66 137.06 90 bottom
PC4505  SC10U25V5KX-GP  [C805H56]  47.53 28.75 180 bottom
PC4506  SCD1U25V2KX-GP  [C402H22]  64.98 134.39 270 bottom
PC4507  SC4D7U6D3V3KX-GP  [C603H36]  72.07 132.9 270 bottom
PC4508  SCD1U25V2KX-GP  [C402H22]  71.83 137.64 270 bottom
PC4509  SC22U6D3V3MX-1-DL-GP  [C603H40]  59.5 130.97 0 bottom
PC4510  SC22U6D3V3MX-1-DL-GP  [C603H40]  69.01 123.01 270 bottom
PC4511  SC22U6D3V3MX-1-DL-GP  [C603H40]  69.01 124.23 270 bottom
PC4512  SC22U6D3V3MX-1-DL-GP  [C603H40]  62.82 128.27 180 bottom
PC4513  SCD1U25V2KX-1-DL-GP  [C402H22]  69.07 125.32 270 bottom
PC4514  SC22U6D3V3MX-1-DL-GP  [C603H40]  53.27 40.1 0 bottom
PC4515  SC22U6D3V3MX-1-DL-GP  [C603H40]  53.38 36.86 180 bottom
PC4516  SC22U6D3V3MX-1-DL-GP  [C603H40]  54.58 37.26 180 bottom
PC4517  SC22U6D3V3MX-1-DL-GP  [C603H40]  52.1 40.1 0 bottom
PC4518  SCD1U16V2KX-3GP  [C402H22]  55.58 36.83 180 bottom
PC4519  SC10U25V5KX-GP  [C805H56]  49.27 28.75 180 bottom
PC4520  SC4D7U6D3V3KX-DLGP  [C603H36]  41.39 40.18 0 bottom
PC4521  SCD1U25V2KX-GP  [C402H22]  39.57 35.1 180 top
PC4522  SCD1U25V2KX-GP  [C402H22]  38.92 34.04 0 bottom
PC4523  SC10U25V5KX-GP  [C805H56]  45.8 28.75 180 bottom
PC4524  SC2D2U10V3KX-1GP  [C603H36]  42.6 40.2 0 bottom
PC4525  SC22U6D3V3MX-1-DL-GP  [C603H40]  62.16 125.08 0 bottom
PC4526  SC1KP50V2KX-1GP  [C402H22]  39.63 39.17 0 bottom
PC4527  SC22U6D3V3MX-1-DL-GP  [C603H40]  54.44 40.08 0 bottom
PC4529  SC22U6D3V3MX-1-DL-GP  [C603H40]  52.16 36.86 180 bottom
PC4530  SCD1U25V2KX-GP  [C402H22]  36.38 38.38 180 bottom
PC4531  SCD1U25V2KX-GP  [C402H22]  38.03 39.72 0 bottom
PC4532  SCD1U25V2KX-GP  [C402H22]  71.83 136.86 270 bottom
PC4533  SC1KP50V2KX-1GP  [C402H22]  72.1 135.79 270 bottom
PC4601  SC2200P50V2KX-2DLGP  [C402H22]  127.84 137.75 270 bottom
PC4602  SCD1U16V2KX-3DLGP  [C402H22]  138.99 143.94 90 top
PC4603  SCD1U25V2KX-1-DL-GP  [C402H22]  128.12 143.16 180 bottom
PC4604  SC330P50V2KX-3-DL-GP  [C402H22]  140.21 145.09 180 bottom
PC4605  SCD047U25V2KX-4-GP  [C402H22]  129.29 140.87 180 bottom
PC4606  SCD22U25V3KX-DL-GP  [C603H36]  134.9 133.73 270 top
PC4607  SC1U10V2KX-1DLGP  [C402H22]  132.3 145.18 0 bottom
PC4608  SCD022U16V2KX-3DLGP  [C402H22]  127.69 140.74 0 bottom
PC4610  SC33P50V2JN-3DLGP  [C402H22]  139.3 143.18 270 top
PC4611  SC2200P50V2KX-2DLGP  [C402H22]  129.64 143.16 180 bottom
PC4612  SC2200P50V2KX-2DLGP  [C402H22]  140.49 142.92 180 top
PC4613  SCD01U25V2KX-3DLGP  [C402H22]  129.54 141.53 180 top
PC4614  SC470P50V2KX-3DLGP  [C402H22]  142.04 143.55 180 top
PC4615  SCD01U50V2KX-1DLGP  [C402H22]  142.75 143.99 270 bottom
PC4616  SC1KP50V2KX-1DLGP  [C402H22]  129.11 140.34 270 top
PC4617  SC1KP50V2KX-1DLGP  [C402H22]  127.92 139.12 180 top
PC4618  SC470P50V2KX-3DLGP  [C402H22]  143.22 143.83 90 top
PC4619  SC1KP50V2KX-1DLGP  [C402H22]  141.84 142.47 90 bottom
PC4620  SCD01U50V2KX-1DLGP  [C402H22]  127.08 139.09 0 top
PC4621  SC680P50V2KX-2GP  [C402H22]  129.17 136.16 90 top
PC4622  SCD01U25V2KX-3DLGP  [C402H22]  140.72 141.91 0 bottom
PC4623  SC2200P50V2KX-2DLGP  [C402H22]  138.86 138.74 90 bottom
PC4624  SC33P50V2JN-3DLGP  [C402H22]  128.81 138.69 90 bottom
PC4625  SCD022U16V2KX-3DLGP  [C402H22]  139.35 136.55 270 bottom
PC4626  SCD022U16V2KX-3DLGP  [C402H22]  137.82 136.55 90 bottom
PC4628  SCD022U16V2KX-3DLGP  [C402H22]  140.59 140.26 0 bottom
PC4629  SC330P50V2KX-3-DL-GP  [C402H22]  129.39 137.87 270 bottom
PC4630  SCD047U25V2KX-4-GP  [C402H22]  141.02 138.48 180 bottom
PC4631  SCD1U25V2KX-1-DL-GP  [C402H22]  126.88 134.11 180 bottom
PC4632  SC2200P50V2KX-2DLGP  [C402H22]  126.77 136.4 270 bottom
PC4633  SCD1U25V2KX-1-DL-GP  [C402H22]  142.17 136.7 270 bottom
PC4634  SCD047U25V2KX-4-GP  [C402H22]  129.14 133.05 270 bottom
PC4635  SCD01U25V2KX-3DLGP  [C402H22]  130.13 134.72 270 bottom
PC4637  SCD01U25V2KX-3DLGP  [C402H22]  131.19 133.12 270 bottom
PC4638  SC330P50V2KX-3-DL-GP  [C402H22]  136.18 136.19 270 bottom
PC4639  SC33P50V2JN-3DLGP  [C402H22]  134.39 134.09 180 bottom
PC4640  SC2200P50V2KX-2DLGP  [C402H22]  135.01 131.63 90 bottom
PC4641  SC330P50V2KX-3-DL-GP  [C402H22]  133.61 133.17 180 bottom
PC4642  SC1KP50V2KX-1DLGP  [C402H22]  131.17 132.34 270 bottom
PC4643  SC1KP50V2KX-1DLGP  [C402H22]  132.16 131.24 90 bottom
PC4644  SCD01U50V2KX-1DLGP  [C402H22]  131.78 130.1 180 bottom
PC4651  SC1KP50V2KX-1DLGP  [C402H22]  141.25 142.92 180 top
PC4652  SCD022U16V2KX-3DLGP  [C402H22]  130.1 135.54 270 bottom
PC4653  SCD047U25V2KX-4-GP  [C402H22]  139.07 140.26 0 bottom
PC4654  SCD022U16V2KX-3DLGP  [C402H22]  139.83 140.26 0 bottom
PC4701  SC10U25V3MX-GP  [C603H40]  79.32 142.43 90 bottom
PC4702  SC10U25V3MX-GP  [C603H40]  79.66 143.97 270 top
PC4703  SC10U25V3MX-GP  [C603H40]  79.25 143.89 90 bottom
PC4704  SC10U25V3MX-GP  [C603H40]  79.68 142.5 270 top
PC4706  SC1KP50V2KX-1DLGP  [C402H22]  77.3 136.2 270 top
PC4707  SCD22U25V3KX-DL-GP  [C603H36]  76.46 143.05 0 top
PC4708  SC1U10V2KX-1DLGP  [C402H22]  77.4 142.32 270 bottom
PC4766  SC1U10V2KX-1DLGP  [C402H22]  75.57 139.42 90 top
PC4802  SC10U25V3MX-GP  [C603H40]  99.32 142.26 90 bottom
PC4803  SC10U25V3MX-GP  [C603H40]  99.77 143.44 270 top
PC4804  SC10U25V3MX-GP  [C603H40]  99.06 143.54 90 bottom
PC4805  SC10U25V3MX-GP  [C603H40]  99.32 142.27 270 top
PC4808  SCD22U25V3KX-DL-GP  [C603H36]  96.52 143.03 0 top
PC4809  SC1U10V2KX-1DLGP  [C402H22]  96.48 142.71 270 bottom
PC4810  SC1KP50V2KX-1DLGP  [C402H22]  94.9 136.19 90 top
PC4811  SCD22U25V3KX-DL-GP  [C603H36]  90.81 143.91 180 bottom
PC4812  SC1U10V2KX-1DLGP  [C402H22]  87.66 143.97 0 bottom
PC4813  SC1KP50V2KX-1DLGP  [C402H22]  88.9 135.79 180 top
PC4814  SC10U25V3MX-GP  [C603H40]  91.84 137.9 0 top
PC4815  SC10U25V3MX-GP  [C603H40]  91.85 137.75 180 bottom
PC4816  SC10U25V3MX-GP  [C603H40]  93.04 137.9 180 bottom
PC4817  SC10U25V3MX-GP  [C603H40]  93.04 137.9 0 top
PC4866  SC1U10V2KX-1DLGP  [C402H22]  93.6 140.62 0 bottom
PC4877  SC1U10V2KX-1DLGP  [C402H22]  89.28 139.37 0 top
PC5001  SC2D2U10V3KX-1DLGP-U  [C603H36]  113.9 140.85 0 bottom
PC5002  SC10U25V5KX-DL-GP  [C805H58]  108.24 142.16 270 bottom
PC5003  SC10U25V5KX-DL-GP  [C805H58]  107.78 140.41 270 bottom
PC5004  SCD1U25V2KX-1-DL-GP  [C402H22]  108.26 143.41 270 bottom
PC5005  SCD22U25V3KX-DL-GP  [C603H36]  111.94 141.43 270 top
PC5102  SCD1U25V2KX-1-DL-GP  [C402H22]  119.97 31.57 90 top
PC5103  SC1U10V2KX-L1-GP  [C402H22]  113.92 29.52 180 top
PC5104  SC22U6D3V3MX-L1-GP  [C603H40]  111.86 40.18 0 bottom
PC5105  SC22U6D3V3MX-L1-GP  [C603H40]  120.23 38.29 180 bottom
PC5106  SC22U6D3V3MX-L1-GP  [C603H40]  111.89 37.8 180 bottom
PC5107  SC22U6D3V3MX-L1-GP  [C603H40]  110.7 40.18 0 bottom
PC5111  SC68P50V2JN-1DLGP  [C402H22]  164.24 117.32 90 bottom
PC5112  SC10U6D3V3MX-DL-GP  [C603H36]  166.59 117.78 270 bottom
PC5113  SC10U6D3V3MX-DL-GP  [C603H36]  166.59 118.96 270 bottom
PC5114  SC1U6D3V1MX-GP  [C0201H14]  119.38 28.04 0 top
PC5115  SC10U25V5KX-L-GP  [C805H56]  120.55 35.71 0 bottom
PC5116  SC10U6D3V3MX-L-GP  [C603H38]  119.21 28.09 180 bottom
PC5117  SC10U6D3V3MX-L-GP  [C603H38]  120.37 28.09 180 bottom
PC5118  SC1500P50V2KX-2GP  [C402H22]  113.16 33.58 0 top
PC5119  SC10U25V5KX-L-GP  [C805H56]  122.33 35.71 0 bottom
PC5120  SC1U10V2KX-1DLGP  [C402H22]  165.26 108.38 270 bottom
PC5121  SC4D7U6D3V2MX-1-GP  [C402H22]  99.75 36.42 270 bottom
PC5122  SCD1U25V2KX-1-DL-GP  [C402H22]  116.49 31.48 270 top
PC5123  SCD1U16V2KX-3DLGP  [C402H22]  118.6 28.04 0 top
PC5124  SC10U6D3V3MX-DL-GP  [C603H36]  166.6 108.61 180 bottom
PC5127  SCD1U25V2KX-1-DL-GP  [C402H22]  161.28 109.08 45 bottom
PC5201  SC22U6D3V3MX-1-DL-GP  [C603H40]  123.32 134.37 270 bottom
PC5202  SC4D7U25V5KX-DL-GP  [C805H54]  115.36 141.04 0 bottom
PC5203  SC22U6D3V3MX-1-DL-GP  [C603H40]  123.32 133.17 270 bottom
PC5204  SCD1U25V2KX-1-DL-GP  [C402H22]  114.62 138.31 180 bottom
